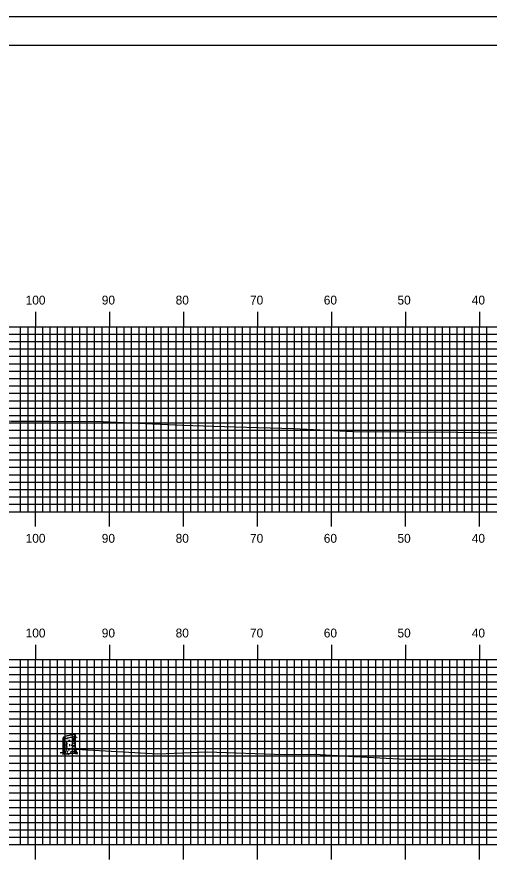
# Model space of a CAD drawing. Extents: x 1772809 to 1773153, y 442591 to 442811.
# Drawn here: x 1772872.6 to 1772936.4, y 442696.2 to 442810.5 of the extents above; entities that cross this region are included whole.
import ezdxf

# ---------------------------------------------------------------- set-up
doc = ezdxf.new("R2010")
doc.units = 0
for name, color, linetype in [('BORDER', 7, 'Continuous'), ('H_V ANNOTATION', 7, 'Continuous'), ('M_Trees_Conifer_Pay', 7, 'Continuous'), ('MAJOR', 7, 'Continuous'), ('MINOR', 7, 'Continuous'), ('PLOT BOUNDARY', 7, 'Continuous'), ('S_Roadway_Centerline', 7, 'Continuous')]:
    doc.layers.add(name, color=color, linetype=linetype)

msp = doc.modelspace()

# ---------------------------------------------------------------- linework, layer by layer
at = {"layer": 'BORDER'}
msp.add_lwpolyline([(1772825.52, 442596.67), (1773145.52, 442596.67), (1773145.52, 442806.67), (1772825.52, 442806.67)], close=True, dxfattribs=at)
at = {"layer": 'M_Trees_Conifer_Pay'}
for p, q in [((1772878.88, 442711.4), (1772878.88, 442713.12)), ((1772878.92, 442713.08), (1772878.92, 442712.61)), ((1772878.98, 442713.07), (1772878.98, 442712.97)), ((1772878.98, 442712.9), (1772878.98, 442712.69)), ((1772879.11, 442713.06), (1772879.11, 442712.83)), ((1772879.11, 442712.79), (1772879.11, 442712.71)), ((1772879.33, 442713.08), (1772879.33, 442712.91)), ((1772879.73, 442712.85), (1772879.73, 442712.75)), ((1772880.12, 442713.12), (1772880.12, 442712.92)), ((1772880.12, 442712.87), (1772880.12, 442712.78)), ((1772880.35, 442713.32), (1772880.35, 442713.1)), ((1772880.35, 442713.01), (1772880.35, 442712.96)), ((1772880.41, 442712.83), (1772880.36, 442712.77)), ((1772880.47, 442713.38), (1772880.47, 442713.22)), ((1772880.47, 442713.15), (1772880.47, 442713.02)), ((1772880.47, 442712.84), (1772880.47, 442712.5)), ((1772880.54, 442711.81), (1772880.54, 442713.45)), ((1772878.92, 442712.54), (1772878.92, 442712.24)), ((1772878.92, 442712.19), (1772878.92, 442711.7)), ((1772878.92, 442711.64), (1772878.92, 442711.4)), ((1772878.98, 442712.64), (1772878.98, 442712.44)), ((1772878.98, 442712.39), (1772878.98, 442712.05)), ((1772878.98, 442712), (1772878.98, 442711.86)), ((1772878.98, 442711.76), (1772878.98, 442711.39)), ((1772879.11, 442712.31), (1772879.11, 442712.17)), ((1772879.11, 442711.9), (1772879.11, 442711.76)), ((1772879.33, 442712.68), (1772879.33, 442712.44)), ((1772879.33, 442712.2), (1772879.33, 442712.04)), ((1772879.33, 442712), (1772879.33, 442711.83)), ((1772879.73, 442712.24), (1772879.73, 442712.16)), ((1772879.73, 442712.14), (1772879.73, 442711.99)), ((1772879.73, 442711.7), (1772879.73, 442711.54)), ((1772880.12, 442712.43), (1772880.12, 442712.33)), ((1772880.12, 442711.96), (1772880.12, 442711.81)), ((1772880.12, 442711.58), (1772880.12, 442711.49)), ((1772880.35, 442712.63), (1772880.35, 442712.49)), ((1772880.35, 442712.38), (1772880.35, 442712.27)), ((1772880.35, 442712.14), (1772880.35, 442712)), ((1772880.35, 442711.77), (1772880.35, 442711.6)), ((1772880.47, 442712.46), (1772880.47, 442712.3)), ((1772880.47, 442712.25), (1772880.47, 442712.04)), ((1772880.47, 442712.01), (1772880.47, 442711.93)), ((1772880.47, 442711.89), (1772880.47, 442711.72)), ((1772879.11, 442711.5), (1772879.11, 442711.4)), ((1772879.11, 442711), (1772879.27, 442711.07)), ((1772879.33, 442711.55), (1772879.33, 442711.4)), ((1772879.54, 442710.94), (1772879.42, 442711))]:
    msp.add_line(p, q, dxfattribs=at)
for points in [[(1772880.32, 442712.91), (1772880.29, 442712.83), (1772880.29, 442712.76), (1772880.32, 442712.7)], [(1772880.36, 442712.95), (1772880.39, 442712.88), (1772880.44, 442712.93), (1772880.5, 442713), (1772880.59, 442713.2), (1772880.66, 442713.24), (1772880.69, 442713.25)], [(1772880.37, 442712.7), (1772880.41, 442712.83), (1772880.47, 442712.94), (1772880.5, 442713.01), (1772880.57, 442713.15)], [(1772880.59, 442713.18), (1772880.66, 442713.19), (1772880.73, 442713.09)], [(1772880.54, 442711.81), (1772880.59, 442711.54), (1772880.61, 442711.27), (1772880.67, 442711.15), (1772880.8, 442711.11), (1772880.57, 442711.08), (1772880.57, 442711.08), (1772880.58, 442711.03), (1772880.82, 442710.94), (1772880.55, 442710.95), (1772880.2, 442710.97), (1772879.87, 442710.96), (1772879.88, 442711.04), (1772879.73, 442710.96), (1772879.54, 442710.94), (1772879.57, 442710.87), (1772879.3, 442710.91), (1772879.08, 442710.89), (1772878.79, 442710.9), (1772879.08, 442710.96), (1772879.11, 442711), (1772878.95, 442711.06), (1772878.71, 442711.07), (1772878.47, 442711.07), (1772878.81, 442711.13), (1772878.85, 442711.21), (1772878.88, 442711.4)], [(1772879.06, 442712.42), (1772879.05, 442712.52), (1772879.09, 442712.5), (1772879.09, 442712.4)], [(1772880.2, 442712.02), (1772880.21, 442711.95), (1772880.25, 442711.96), (1772880.24, 442712.13)], [(1772880.47, 442711.66), (1772880.47, 442711.52), (1772880.52, 442711.45), (1772880.53, 442711.25)], [(1772878.92, 442711.35), (1772878.9, 442711.27), (1772878.88, 442711.18)], [(1772879, 442711.33), (1772879.01, 442711.21), (1772878.96, 442711.12), (1772878.95, 442711.06)], [(1772879.17, 442711.36), (1772879.17, 442711.22), (1772879.08, 442711.12)], [(1772879.39, 442711.11), (1772879.46, 442711.21), (1772879.49, 442711.35)], [(1772879.88, 442711.04), (1772879.95, 442711.19), (1772879.96, 442711.29)], [(1772880.13, 442711.41), (1772880.14, 442711.29), (1772880.22, 442711.24)], [(1772880.41, 442711.02), (1772880.39, 442711.16), (1772880.32, 442711.29)], [(1772880.37, 442711.52), (1772880.44, 442711.41), (1772880.45, 442711.24), (1772880.57, 442711.08)]]:
    msp.add_lwpolyline(points, dxfattribs=at)
for centre, radius, start, end in [((1772878.95, 442713.09), 0.0817, 132.3887, 146.7194), ((1772878.93, 442713.11), 0.0527, 146.7194, 156.5158), ((1772878.91, 442713.12), 0.0314, 156.5158, 169.2194), ((1772878.9, 442713.12), 0.0264, 169.2194, 180.0315), ((1772878.9, 442713.12), 0.0226, 180.0315, 191.7194), ((1772878.9, 442713.12), 0.0226, 191.7194, 203.4074), ((1772878.9, 442713.12), 0.0264, 203.4074, 214.2194), ((1772878.91, 442713.12), 0.0314, 214.2194, 226.923), ((1772878.91, 442712.94), 0.0334, 163.9485, 180), ((1772878.91, 442712.94), 0.0334, 180, 196.0515), ((1772878.92, 442712.94), 0.0441, 196.0515, 210), ((1772878.94, 442712.95), 0.0624, 210, 228.7494), ((1772878.92, 442713.14), 0.0527, 226.923, 236.7194), ((1772878.94, 442713.16), 0.0817, 236.7194, 251.0501), ((1772879.01, 442713.03), 0.172, 228.7494, 240), ((1772879.07, 442712.97), 0.251, 124.2194, 132.3887), ((1772878.99, 442713.32), 0.251, 251.0501, 259.2194), ((1772879.38, 442712.51), 0.802, 108.0594, 124.2194), ((1772879.21, 442713.38), 0.571, 240, 240.3367), ((1772879.1, 442713.86), 0.802, 259.2194, 275.3794), ((1772879.21, 442713.38), 0.571, 246.8597, 257.9846), ((1772880.73, 442708.35), 5.18, 101.7194, 108.0594), ((1772878.69, 442718.22), 5.18, 275.3794, 281.7194), ((1772879.71, 442717.13), 4.12, 264.6955, 266.7331), ((1772879.71, 442716.9), 4.12, 268.0751, 270), ((1772880.73, 442708.35), 5.18, 95.3794, 101.7194), ((1772879.71, 442716.9), 4.12, 270, 270.3581), ((1772878.69, 442718.22), 5.18, 281.7194, 288.0594), ((1772879.71, 442716.9), 4.12, 275.7849, 277.0558), ((1772879.71, 442717.13), 4.12, 276.238, 278.1032), ((1772880.32, 442712.71), 0.802, 79.2194, 95.3794), ((1772880.04, 442714.06), 0.802, 288.0594, 304.2194), ((1772880.21, 442713.61), 0.571, 278.1032, 284.3667), ((1772880.21, 442713.77), 0.571, 284.4317, 292.4132), ((1772880.43, 442713.25), 0.251, 71.0501, 79.2194), ((1772880.21, 442713.61), 0.571, 297.0237, 300), ((1772880.35, 442713.6), 0.251, 304.2194, 312.3887), ((1772880.41, 442713.42), 0.172, 300, 311.2506), ((1772880.41, 442713.27), 0.172, 300, 311.2506), ((1772880.48, 442713.41), 0.0817, 56.7194, 71.0501), ((1772880.47, 442713.48), 0.0817, 312.3887, 326.7194), ((1772880.48, 442713.34), 0.0624, 311.2506, 330), ((1772880.48, 442713.18), 0.0624, 311.2506, 330), ((1772880.5, 442713.43), 0.0527, 46.923, 56.7194), ((1772880.51, 442713.45), 0.0314, 34.2194, 46.923), ((1772880.49, 442713.46), 0.0527, 326.7194, 336.5158), ((1772880.51, 442713.45), 0.0264, 23.4074, 34.2194), ((1772880.52, 442713.45), 0.0226, 11.7194, 23.4074), ((1772880.52, 442713.45), 0.0226, 0.0315, 11.7194), ((1772880.51, 442713.45), 0.0314, 336.5158, 349.2194), ((1772880.51, 442713.45), 0.0264, 349.2194, 0.0315), ((1772880.5, 442713.33), 0.0441, 330, 343.9485), ((1772880.51, 442713.33), 0.0334, 343.9485, 354.2151), ((1772880.51, 442713.17), 0.0334, 343.9485, 354.2151), ((1772880.5, 442713.18), 0.0441, 330, 343.9485), ((1772880.51, 442712.73), 0.0334, 343.9485, 354.2151), ((1772878.91, 442712.49), 0.0334, 163.9485, 180), ((1772878.91, 442712.49), 0.0334, 180, 196.0515), ((1772878.92, 442712.5), 0.0441, 196.0515, 210), ((1772878.94, 442712.5), 0.0624, 210, 228.7494), ((1772878.91, 442712.28), 0.0334, 163.9485, 180), ((1772878.91, 442712.28), 0.0334, 180, 196.0515), ((1772878.92, 442712.29), 0.0441, 196.0515, 210), ((1772878.94, 442712.29), 0.0624, 210, 228.7494), ((1772878.91, 442712.05), 0.0334, 163.9485, 180), ((1772878.91, 442712.05), 0.0334, 180, 196.0515), ((1772878.92, 442712.05), 0.0441, 196.0515, 210), ((1772878.94, 442712.06), 0.0624, 210, 228.7494), ((1772878.91, 442711.85), 0.0334, 163.9485, 180), ((1772878.91, 442711.65), 0.0334, 163.9485, 180), ((1772878.91, 442711.65), 0.0334, 180, 196.0515), ((1772878.92, 442711.66), 0.0441, 196.0515, 210), ((1772878.94, 442711.66), 0.0624, 210, 228.7494), ((1772879.01, 442712.59), 0.172, 228.7494, 240), ((1772879.01, 442712.38), 0.172, 228.7494, 240), ((1772879.01, 442712.14), 0.172, 228.7494, 240), ((1772879.01, 442711.75), 0.172, 228.7494, 240), ((1772879.21, 442713.17), 0.571, 240, 247.0587), ((1772879.21, 442712.93), 0.571, 240, 240.3367), ((1772879.21, 442712.72), 0.571, 240, 246.8597), ((1772879.21, 442712.49), 0.571, 240, 246.8597), ((1772879.2, 442712.29), 0.571, 241.2369, 248.0268), ((1772879.21, 442712.09), 0.571, 240, 246.8597), ((1772879.21, 442712.72), 0.571, 259.2707, 261.8968), ((1772879.71, 442716.24), 4.12, 261.8968, 263.1474), ((1772879.71, 442715.81), 4.12, 263.4991, 265.8397), ((1772879.71, 442716.45), 4.12, 264.081, 266.6676), ((1772879.71, 442716), 4.12, 264.716, 266.3193), ((1772879.71, 442716.24), 4.12, 270, 270.3581), ((1772879.71, 442716.24), 4.12, 273.1493, 275.4569), ((1772879.71, 442716.69), 4.12, 273.7052, 275.9504), ((1772879.71, 442716.45), 4.12, 277.6125, 278.1032), ((1772880.21, 442712.93), 0.571, 278.1032, 286.9296), ((1772880.21, 442713.17), 0.571, 284.4493, 297.0429), ((1772880.21, 442712.49), 0.571, 285.3983, 297.1896), ((1772880.21, 442712.09), 0.571, 288.5067, 297.2721), ((1772880.21, 442712.29), 0.571, 289.2907, 300), ((1772880.21, 442712.93), 0.571, 297.1896, 300), ((1772880.21, 442712.72), 0.571, 297.1896, 300), ((1772880.41, 442712.59), 0.172, 300, 311.2506), ((1772880.41, 442712.38), 0.172, 300, 311.2506), ((1772880.41, 442711.94), 0.172, 300, 311.2506), ((1772880.48, 442712.5), 0.0624, 311.2506, 330), ((1772880.48, 442712.29), 0.0624, 311.2506, 330), ((1772880.48, 442711.86), 0.0624, 311.2506, 330), ((1772880.5, 442712.5), 0.0441, 330, 343.9485), ((1772880.5, 442712.29), 0.0441, 330, 343.9485), ((1772880.5, 442711.85), 0.0441, 330, 343.9485), ((1772880.51, 442712.49), 0.0334, 343.9485, 354.2151), ((1772880.51, 442712.28), 0.0334, 343.9485, 354.2151), ((1772880.51, 442711.85), 0.0334, 343.9485, 354.2151), ((1772878.91, 442711.43), 0.0334, 163.9485, 180), ((1772878.91, 442711.43), 0.0334, 180, 196.0515), ((1772878.92, 442711.44), 0.0441, 196.0515, 210), ((1772878.94, 442711.44), 0.0624, 210, 228.7494), ((1772879.01, 442711.53), 0.172, 228.7494, 240), ((1772879.21, 442711.87), 0.571, 240, 244.5314), ((1772879.71, 442715.39), 4.12, 262.4438, 263.512), ((1772879.71, 442715.61), 4.12, 267.8117, 270), ((1772879.71, 442715.61), 4.12, 270, 270.1328), ((1772879.71, 442715.61), 4.12, 275.7849, 276.7896), ((1772879.71, 442715.39), 4.12, 277.3684, 278.1032), ((1772880.21, 442711.87), 0.571, 278.1032, 281.637), ((1772880.41, 442711.53), 0.172, 300, 311.2506), ((1772880.48, 442711.44), 0.0624, 311.2506, 330), ((1772880.5, 442711.44), 0.0441, 330, 343.9485), ((1772880.51, 442711.43), 0.0334, 343.9485, 354.2151)]:
    msp.add_arc(centre, radius, start, end, dxfattribs=at)
at = {"layer": 'MAJOR'}
for p, q in [((1772875.12, 442770.67), (1772875.12, 442768.67)), ((1772885.12, 442770.67), (1772885.12, 442768.67)), ((1772895.12, 442770.67), (1772895.12, 442768.67)), ((1772905.12, 442770.67), (1772905.12, 442768.67)), ((1772915.12, 442770.67), (1772915.12, 442768.67)), ((1772925.12, 442770.67), (1772925.12, 442768.67)), ((1772935.12, 442770.67), (1772935.12, 442768.67)), ((1772835.12, 442768.67), (1773115.12, 442768.67)), ((1772835.12, 442768.67), (1773115.12, 442768.67)), ((1772875.12, 442743.67), (1772875.12, 442768.67)), ((1772885.12, 442743.67), (1772885.12, 442768.67)), ((1772895.12, 442743.67), (1772895.12, 442768.67)), ((1772905.12, 442743.67), (1772905.12, 442768.67)), ((1772915.12, 442743.67), (1772915.12, 442768.67)), ((1772925.12, 442743.67), (1772925.12, 442768.67)), ((1772935.12, 442743.67), (1772935.12, 442768.67)), ((1772835.12, 442763.67), (1773115.12, 442763.67)), ((1772835.12, 442758.67), (1773115.12, 442758.67)), ((1772835.12, 442753.67), (1773115.12, 442753.67)), ((1772835.12, 442748.67), (1773115.12, 442748.67)), ((1772835.12, 442743.67), (1773115.12, 442743.67)), ((1772835.12, 442743.67), (1773115.12, 442743.67)), ((1772875.12, 442741.66), (1772875.12, 442743.67)), ((1772885.12, 442741.66), (1772885.12, 442743.67)), ((1772895.12, 442741.66), (1772895.12, 442743.67)), ((1772905.12, 442741.66), (1772905.12, 442743.67)), ((1772915.12, 442741.66), (1772915.12, 442743.67)), ((1772925.12, 442741.66), (1772925.12, 442743.67)), ((1772935.12, 442741.66), (1772935.12, 442743.67)), ((1772875.12, 442725.67), (1772875.12, 442723.67)), ((1772885.12, 442725.67), (1772885.12, 442723.67)), ((1772895.12, 442725.67), (1772895.12, 442723.67)), ((1772905.12, 442725.67), (1772905.12, 442723.67)), ((1772915.12, 442725.67), (1772915.12, 442723.67)), ((1772925.12, 442725.67), (1772925.12, 442723.67)), ((1772935.12, 442725.67), (1772935.12, 442723.67)), ((1772835.12, 442723.67), (1773115.12, 442723.67)), ((1772835.12, 442723.67), (1773115.12, 442723.67)), ((1772875.12, 442698.67), (1772875.12, 442723.67)), ((1772885.12, 442698.67), (1772885.12, 442723.67)), ((1772895.12, 442698.67), (1772895.12, 442723.67)), ((1772905.12, 442698.67), (1772905.12, 442723.67)), ((1772915.12, 442698.67), (1772915.12, 442723.67)), ((1772925.12, 442698.67), (1772925.12, 442723.67)), ((1772935.12, 442698.67), (1772935.12, 442723.67)), ((1772835.12, 442718.67), (1773115.12, 442718.67)), ((1772835.12, 442713.67), (1773115.12, 442713.67)), ((1772835.12, 442708.67), (1773115.12, 442708.67)), ((1772835.12, 442703.67), (1773115.12, 442703.67)), ((1772835.12, 442698.67), (1773115.12, 442698.67)), ((1772835.12, 442698.67), (1773115.12, 442698.67)), ((1772875.12, 442696.66), (1772875.12, 442698.67)), ((1772885.12, 442696.66), (1772885.12, 442698.67)), ((1772895.12, 442696.66), (1772895.12, 442698.67)), ((1772905.12, 442696.66), (1772905.12, 442698.67)), ((1772915.12, 442696.66), (1772915.12, 442698.67)), ((1772925.12, 442696.66), (1772925.12, 442698.67)), ((1772935.12, 442696.66), (1772935.12, 442698.67))]:
    msp.add_line(p, q, dxfattribs=at)
at = {"layer": 'MINOR'}
for p, q in [((1772835.12, 442767.67), (1773115.12, 442767.67)), ((1772873.12, 442743.67), (1772873.12, 442768.67)), ((1772874.12, 442743.67), (1772874.12, 442768.67)), ((1772876.12, 442743.67), (1772876.12, 442768.67)), ((1772877.12, 442743.67), (1772877.12, 442768.67)), ((1772878.12, 442743.67), (1772878.12, 442768.67)), ((1772879.12, 442743.67), (1772879.12, 442768.67)), ((1772880.12, 442743.67), (1772880.12, 442768.67)), ((1772881.12, 442743.67), (1772881.12, 442768.67)), ((1772882.12, 442743.67), (1772882.12, 442768.67)), ((1772883.12, 442743.67), (1772883.12, 442768.67)), ((1772884.12, 442743.67), (1772884.12, 442768.67)), ((1772886.12, 442743.67), (1772886.12, 442768.67)), ((1772887.12, 442743.67), (1772887.12, 442768.67)), ((1772888.12, 442743.67), (1772888.12, 442768.67)), ((1772889.12, 442743.67), (1772889.12, 442768.67)), ((1772890.12, 442743.67), (1772890.12, 442768.67)), ((1772891.12, 442743.67), (1772891.12, 442768.67)), ((1772892.12, 442743.67), (1772892.12, 442768.67)), ((1772893.12, 442743.67), (1772893.12, 442768.67)), ((1772894.12, 442743.67), (1772894.12, 442768.67)), ((1772896.12, 442743.67), (1772896.12, 442768.67)), ((1772897.12, 442743.67), (1772897.12, 442768.67)), ((1772898.12, 442743.67), (1772898.12, 442768.67)), ((1772899.12, 442743.67), (1772899.12, 442768.67)), ((1772900.12, 442743.67), (1772900.12, 442768.67)), ((1772901.12, 442743.67), (1772901.12, 442768.67)), ((1772902.12, 442743.67), (1772902.12, 442768.67)), ((1772903.12, 442743.67), (1772903.12, 442768.67)), ((1772904.12, 442743.67), (1772904.12, 442768.67)), ((1772906.12, 442743.67), (1772906.12, 442768.67)), ((1772907.12, 442743.67), (1772907.12, 442768.67)), ((1772908.12, 442743.67), (1772908.12, 442768.67)), ((1772909.12, 442743.67), (1772909.12, 442768.67)), ((1772910.12, 442743.67), (1772910.12, 442768.67)), ((1772911.12, 442743.67), (1772911.12, 442768.67)), ((1772912.12, 442743.67), (1772912.12, 442768.67)), ((1772913.12, 442743.67), (1772913.12, 442768.67)), ((1772914.12, 442743.67), (1772914.12, 442768.67)), ((1772916.12, 442743.67), (1772916.12, 442768.67)), ((1772917.12, 442743.67), (1772917.12, 442768.67)), ((1772918.12, 442743.67), (1772918.12, 442768.67)), ((1772919.12, 442743.67), (1772919.12, 442768.67)), ((1772920.12, 442743.67), (1772920.12, 442768.67)), ((1772921.12, 442743.67), (1772921.12, 442768.67)), ((1772922.12, 442743.67), (1772922.12, 442768.67)), ((1772923.12, 442743.67), (1772923.12, 442768.67)), ((1772924.12, 442743.67), (1772924.12, 442768.67)), ((1772926.12, 442743.67), (1772926.12, 442768.67)), ((1772927.12, 442743.67), (1772927.12, 442768.67)), ((1772928.12, 442743.67), (1772928.12, 442768.67)), ((1772929.12, 442743.67), (1772929.12, 442768.67)), ((1772930.12, 442743.67), (1772930.12, 442768.67)), ((1772931.12, 442743.67), (1772931.12, 442768.67)), ((1772932.12, 442743.67), (1772932.12, 442768.67)), ((1772933.12, 442743.67), (1772933.12, 442768.67)), ((1772934.12, 442743.67), (1772934.12, 442768.67)), ((1772936.12, 442743.67), (1772936.12, 442768.67)), ((1772835.12, 442766.67), (1773115.12, 442766.67)), ((1772835.12, 442765.67), (1773115.12, 442765.67)), ((1772835.12, 442764.67), (1773115.12, 442764.67)), ((1772835.12, 442762.67), (1773115.12, 442762.67)), ((1772835.12, 442761.67), (1773115.12, 442761.67)), ((1772835.12, 442760.67), (1773115.12, 442760.67)), ((1772835.12, 442759.67), (1773115.12, 442759.67)), ((1772835.12, 442757.67), (1773115.12, 442757.67)), ((1772835.12, 442756.67), (1773115.12, 442756.67)), ((1772835.12, 442755.67), (1773115.12, 442755.67)), ((1772835.12, 442754.67), (1773115.12, 442754.67)), ((1772835.12, 442752.67), (1773115.12, 442752.67)), ((1772835.12, 442751.67), (1773115.12, 442751.67)), ((1772835.12, 442750.67), (1773115.12, 442750.67)), ((1772835.12, 442749.67), (1773115.12, 442749.67)), ((1772835.12, 442747.67), (1773115.12, 442747.67)), ((1772835.12, 442746.67), (1773115.12, 442746.67)), ((1772835.12, 442745.67), (1773115.12, 442745.67)), ((1772835.12, 442744.67), (1773115.12, 442744.67)), ((1772873.12, 442698.67), (1772873.12, 442723.67)), ((1772874.12, 442698.67), (1772874.12, 442723.67)), ((1772876.12, 442698.67), (1772876.12, 442723.67)), ((1772877.12, 442698.67), (1772877.12, 442723.67)), ((1772878.12, 442698.67), (1772878.12, 442723.67)), ((1772879.12, 442698.67), (1772879.12, 442723.67)), ((1772880.12, 442698.67), (1772880.12, 442723.67)), ((1772881.12, 442698.67), (1772881.12, 442723.67)), ((1772882.12, 442698.67), (1772882.12, 442723.67)), ((1772883.12, 442698.67), (1772883.12, 442723.67)), ((1772884.12, 442698.67), (1772884.12, 442723.67)), ((1772886.12, 442698.67), (1772886.12, 442723.67)), ((1772887.12, 442698.67), (1772887.12, 442723.67)), ((1772888.12, 442698.67), (1772888.12, 442723.67)), ((1772889.12, 442698.67), (1772889.12, 442723.67)), ((1772890.12, 442698.67), (1772890.12, 442723.67)), ((1772891.12, 442698.67), (1772891.12, 442723.67)), ((1772892.12, 442698.67), (1772892.12, 442723.67)), ((1772893.12, 442698.67), (1772893.12, 442723.67)), ((1772894.12, 442698.67), (1772894.12, 442723.67)), ((1772896.12, 442698.67), (1772896.12, 442723.67)), ((1772897.12, 442698.67), (1772897.12, 442723.67)), ((1772898.12, 442698.67), (1772898.12, 442723.67)), ((1772899.12, 442698.67), (1772899.12, 442723.67)), ((1772900.12, 442698.67), (1772900.12, 442723.67)), ((1772901.12, 442698.67), (1772901.12, 442723.67)), ((1772902.12, 442698.67), (1772902.12, 442723.67)), ((1772903.12, 442698.67), (1772903.12, 442723.67)), ((1772904.12, 442698.67), (1772904.12, 442723.67)), ((1772906.12, 442698.67), (1772906.12, 442723.67)), ((1772907.12, 442698.67), (1772907.12, 442723.67)), ((1772908.12, 442698.67), (1772908.12, 442723.67)), ((1772909.12, 442698.67), (1772909.12, 442723.67)), ((1772910.12, 442698.67), (1772910.12, 442723.67)), ((1772911.12, 442698.67), (1772911.12, 442723.67)), ((1772912.12, 442698.67), (1772912.12, 442723.67)), ((1772913.12, 442698.67), (1772913.12, 442723.67)), ((1772914.12, 442698.67), (1772914.12, 442723.67)), ((1772916.12, 442698.67), (1772916.12, 442723.67)), ((1772917.12, 442698.67), (1772917.12, 442723.67)), ((1772918.12, 442698.67), (1772918.12, 442723.67)), ((1772919.12, 442698.67), (1772919.12, 442723.67)), ((1772920.12, 442698.67), (1772920.12, 442723.67)), ((1772921.12, 442698.67), (1772921.12, 442723.67)), ((1772922.12, 442698.67), (1772922.12, 442723.67)), ((1772923.12, 442698.67), (1772923.12, 442723.67)), ((1772924.12, 442698.67), (1772924.12, 442723.67)), ((1772926.12, 442698.67), (1772926.12, 442723.67)), ((1772927.12, 442698.67), (1772927.12, 442723.67)), ((1772928.12, 442698.67), (1772928.12, 442723.67)), ((1772929.12, 442698.67), (1772929.12, 442723.67)), ((1772930.12, 442698.67), (1772930.12, 442723.67)), ((1772931.12, 442698.67), (1772931.12, 442723.67)), ((1772932.12, 442698.67), (1772932.12, 442723.67)), ((1772933.12, 442698.67), (1772933.12, 442723.67)), ((1772934.12, 442698.67), (1772934.12, 442723.67)), ((1772936.12, 442698.67), (1772936.12, 442723.67)), ((1772835.12, 442722.67), (1773115.12, 442722.67)), ((1772835.12, 442721.67), (1773115.12, 442721.67)), ((1772835.12, 442720.67), (1773115.12, 442720.67)), ((1772835.12, 442719.67), (1773115.12, 442719.67)), ((1772835.12, 442717.67), (1773115.12, 442717.67)), ((1772835.12, 442716.67), (1773115.12, 442716.67)), ((1772835.12, 442715.67), (1773115.12, 442715.67)), ((1772835.12, 442714.67), (1773115.12, 442714.67)), ((1772835.12, 442712.67), (1773115.12, 442712.67)), ((1772835.12, 442711.67), (1773115.12, 442711.67)), ((1772835.12, 442710.67), (1773115.12, 442710.67)), ((1772835.12, 442709.67), (1773115.12, 442709.67)), ((1772835.12, 442707.67), (1773115.12, 442707.67)), ((1772835.12, 442706.67), (1773115.12, 442706.67)), ((1772835.12, 442705.67), (1773115.12, 442705.67)), ((1772835.12, 442704.67), (1773115.12, 442704.67)), ((1772835.12, 442702.67), (1773115.12, 442702.67)), ((1772835.12, 442701.67), (1773115.12, 442701.67)), ((1772835.12, 442700.67), (1773115.12, 442700.67)), ((1772835.12, 442699.67), (1773115.12, 442699.67))]:
    msp.add_line(p, q, dxfattribs=at)
at = {"layer": 'PLOT BOUNDARY'}
msp.add_lwpolyline([(1772809.33, 442590.55), (1773149.33, 442590.55), (1773149.33, 442810.55), (1772809.33, 442810.55)], close=True, dxfattribs=at)
at = {"layer": 'S_Roadway_Centerline'}
for points in [[(1772835.12, 442756.56), (1772836.57, 442756.52), (1772845.82, 442756.52), (1772851.23, 442756.4), (1772860.16, 442756.09), (1772867.64, 442755.93), (1772871.84, 442755.92), (1772876.95, 442755.9), (1772884.26, 442755.84), (1772889.97, 442755.61), (1772895, 442755.35), (1772902.09, 442755.16), (1772910.01, 442754.92), (1772918.1, 442754.52), (1772932.13, 442754.44), (1772941.59, 442754.28)], [(1772835.12, 442712.49), (1772840.85, 442712.37), (1772843.73, 442712.33), (1772846.26, 442712.22), (1772865.24, 442711.67), (1772866.83, 442711.63), (1772878.99, 442711.64), (1772888.57, 442711.11), (1772891.65, 442710.96), (1772898.35, 442711.19), (1772908.72, 442710.86), (1772912.83, 442710.88), (1772918.2, 442710.59), (1772925.13, 442710.21), (1772930.63, 442710.21), (1772936.63, 442710.11)]]:
    msp.add_lwpolyline(points, dxfattribs=at)

# ---------------------------------------------------------------- texts
at = {"layer": 'H_V ANNOTATION'}
for s, p in [('100', (1772873.8, 442771.67)), ('90', (1772884.09, 442771.67)), ('80', (1772894.07, 442771.67)), ('70', (1772904.12, 442771.67)), ('60', (1772914.09, 442771.67)), ('50', (1772924.05, 442771.67)), ('40', (1772934.09, 442771.67)), ('100', (1772873.8, 442739.47)), ('90', (1772884.09, 442739.47)), ('80', (1772894.07, 442739.47)), ('70', (1772904.12, 442739.47)), ('60', (1772914.09, 442739.47)), ('50', (1772924.05, 442739.47)), ('40', (1772934.09, 442739.47)), ('100', (1772873.8, 442726.67)), ('90', (1772884.09, 442726.67)), ('80', (1772894.07, 442726.67)), ('70', (1772904.12, 442726.67)), ('60', (1772914.09, 442726.67)), ('50', (1772924.05, 442726.67)), ('40', (1772934.09, 442726.67))]:
    msp.add_text(s, height=1.2, dxfattribs=at).set_placement(p)

doc.saveas('drawing.dxf')
